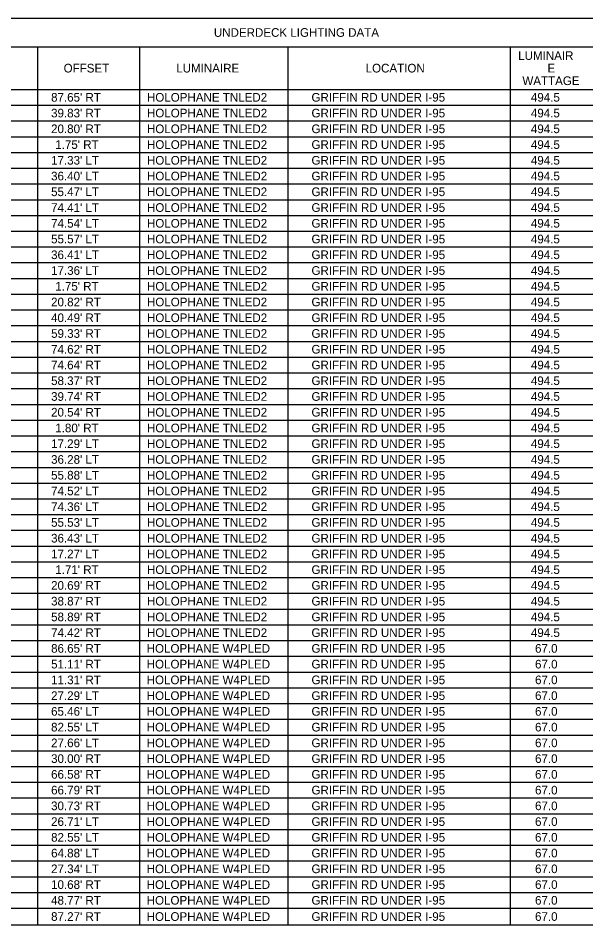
# Model space of a CAD drawing. Extents: x -816.7 to -800.9, y -2209.6 to -2187.8.
# Drawn here: x -810.37 to -805.77, y -2207.45 to -2200.11 of the extents above; entities that cross this region are included whole.
import ezdxf

# ---------------------------------------------------------------- set-up
doc = ezdxf.new("R2010")
doc.units = 0
for name, color, linetype in [('PlotBorder_dp', 7, 'Continuous'), ('SheetBorder_dp', 7, 'Continuous'), ('SheetLines_dp', 7, 'Continuous'), ('TextMinor', 7, 'Continuous')]:
    doc.layers.add(name, color=color, linetype=linetype)

msp = doc.modelspace()

# ---------------------------------------------------------------- linework, layer by layer
at = {"layer": 'PlotBorder_dp'}
for p, q in [((-810.2111, -2200.3435), (-810.2111, -2201.326)), ((-810.2111, -2200.3435), (-810.2111, -2207.4535)), ((-809.3861, -2200.3435), (-809.3861, -2207.4535)), ((-809.3861, -2200.3435), (-809.3861, -2207.4535)), ((-808.1861, -2200.3435), (-808.1861, -2207.4535)), ((-808.1861, -2200.3435), (-808.1861, -2207.4535)), ((-806.3861, -2200.3435), (-806.3861, -2207.4535)), ((-806.3861, -2200.3435), (-806.3861, -2207.4535)), ((-813.1586, -2200.6885), (-802.8536, -2200.6885)), ((-810.2111, -2201.4535), (-810.2111, -2205.7885)), ((-810.2111, -2205.916), (-810.2111, -2207.4535))]:
    msp.add_line(p, q, dxfattribs=at)
at = {"layer": 'SheetLines_dp'}
for p, q in [((-813.1586, -2200.111), (-802.8536, -2200.111)), ((-813.1586, -2200.3435), (-802.8536, -2200.3435)), ((-813.1586, -2200.3435), (-802.8536, -2200.3435)), ((-813.1586, -2207.4535), (-802.8536, -2207.4535))]:
    msp.add_line(p, q, dxfattribs=at)
at = {"layer": 'TextMinor'}
for p, q in [((-813.1586, -2200.6885), (-802.8536, -2200.6885)), ((-813.1586, -2200.816), (-802.8536, -2200.816)), ((-813.1586, -2200.816), (-802.8536, -2200.816)), ((-813.1586, -2200.9435), (-802.8536, -2200.9435)), ((-813.1586, -2200.9435), (-802.8536, -2200.9435)), ((-813.1586, -2201.071), (-802.8536, -2201.071)), ((-813.1586, -2201.071), (-802.8536, -2201.071)), ((-813.1586, -2201.1985), (-802.8536, -2201.1985)), ((-813.1586, -2201.1985), (-802.8536, -2201.1985)), ((-813.1586, -2201.326), (-802.8536, -2201.326)), ((-813.1586, -2201.326), (-802.8536, -2201.326)), ((-813.1586, -2201.4535), (-802.8536, -2201.4535)), ((-810.2111, -2201.4535), (-802.8536, -2201.4535)), ((-813.1586, -2201.581), (-802.8536, -2201.581)), ((-813.1586, -2201.581), (-802.8536, -2201.581)), ((-813.1586, -2201.7085), (-802.8536, -2201.7085)), ((-813.1586, -2201.7085), (-802.8536, -2201.7085)), ((-813.1586, -2201.836), (-802.8536, -2201.836)), ((-813.1586, -2201.836), (-802.8536, -2201.836)), ((-813.1586, -2201.9635), (-802.8536, -2201.9635)), ((-813.1586, -2201.9635), (-802.8536, -2201.9635)), ((-813.1586, -2202.091), (-802.8536, -2202.091)), ((-813.1586, -2202.091), (-802.8536, -2202.091)), ((-813.1586, -2202.2185), (-802.8536, -2202.2185)), ((-813.1586, -2202.2185), (-802.8536, -2202.2185)), ((-813.1586, -2202.346), (-802.8536, -2202.346)), ((-813.1586, -2202.346), (-802.8536, -2202.346)), ((-813.1586, -2202.4735), (-802.8536, -2202.4735)), ((-813.1586, -2202.4735), (-802.8536, -2202.4735)), ((-813.1586, -2202.601), (-802.8536, -2202.601)), ((-813.1586, -2202.601), (-802.8536, -2202.601)), ((-813.1586, -2202.7285), (-802.8536, -2202.7285)), ((-813.1586, -2202.7285), (-802.8536, -2202.7285)), ((-813.1586, -2202.856), (-802.8536, -2202.856)), ((-813.1586, -2202.856), (-802.8536, -2202.856)), ((-813.1586, -2202.9835), (-802.8536, -2202.9835)), ((-813.1586, -2202.9835), (-802.8536, -2202.9835)), ((-813.1586, -2203.111), (-802.8536, -2203.111)), ((-813.1586, -2203.111), (-802.8536, -2203.111)), ((-813.1586, -2203.2385), (-802.8536, -2203.2385)), ((-813.1586, -2203.2385), (-802.8536, -2203.2385)), ((-813.1586, -2203.366), (-802.8536, -2203.366)), ((-813.1586, -2203.366), (-802.8536, -2203.366)), ((-813.1586, -2203.4935), (-802.8536, -2203.4935)), ((-813.1586, -2203.4935), (-802.8536, -2203.4935)), ((-813.1586, -2203.621), (-802.8536, -2203.621)), ((-813.1586, -2203.621), (-802.8536, -2203.621)), ((-813.1586, -2203.7485), (-802.8536, -2203.7485)), ((-813.1586, -2203.7485), (-802.8536, -2203.7485)), ((-813.1586, -2203.876), (-802.8536, -2203.876)), ((-813.1586, -2203.876), (-802.8536, -2203.876)), ((-813.1586, -2204.0035), (-802.8536, -2204.0035)), ((-813.1586, -2204.0035), (-802.8536, -2204.0035)), ((-813.1586, -2204.131), (-802.8536, -2204.131)), ((-813.1586, -2204.131), (-802.8536, -2204.131)), ((-813.1586, -2204.2585), (-802.8536, -2204.2585)), ((-813.1586, -2204.2585), (-802.8536, -2204.2585)), ((-813.1586, -2204.386), (-802.8536, -2204.386)), ((-813.1586, -2204.386), (-802.8536, -2204.386)), ((-813.1586, -2204.5135), (-802.8536, -2204.5135)), ((-813.1586, -2204.5135), (-802.8536, -2204.5135)), ((-813.1586, -2204.641), (-802.8536, -2204.641)), ((-813.1586, -2204.641), (-802.8536, -2204.641)), ((-813.1586, -2204.7685), (-802.8536, -2204.7685)), ((-813.1586, -2204.7685), (-802.8536, -2204.7685)), ((-813.1586, -2204.896), (-802.8536, -2204.896)), ((-813.1586, -2204.896), (-802.8536, -2204.896)), ((-813.1586, -2205.0235), (-802.8536, -2205.0235)), ((-813.1586, -2205.0235), (-802.8536, -2205.0235)), ((-813.1586, -2205.151), (-802.8536, -2205.151)), ((-813.1586, -2205.2785), (-802.8536, -2205.2785)), ((-813.1586, -2205.2785), (-802.8536, -2205.2785)), ((-813.1586, -2205.406), (-802.8536, -2205.406)), ((-813.1586, -2205.406), (-802.8536, -2205.406)), ((-813.1586, -2205.5335), (-802.8536, -2205.5335)), ((-813.1586, -2205.5335), (-802.8536, -2205.5335)), ((-813.1586, -2205.661), (-802.8536, -2205.661)), ((-813.1586, -2205.661), (-802.8536, -2205.661)), ((-813.1586, -2205.7885), (-802.8536, -2205.7885)), ((-813.1586, -2205.7885), (-802.8536, -2205.7885)), ((-813.1586, -2205.916), (-802.8536, -2205.916)), ((-810.2111, -2205.916), (-802.8536, -2205.916)), ((-813.1586, -2206.0435), (-802.8536, -2206.0435)), ((-813.1586, -2206.0435), (-802.8536, -2206.0435)), ((-813.1586, -2206.171), (-802.8536, -2206.171)), ((-813.1586, -2206.171), (-802.8536, -2206.171)), ((-813.1586, -2206.2985), (-802.8536, -2206.2985)), ((-813.1586, -2206.2985), (-802.8536, -2206.2985)), ((-813.1586, -2206.426), (-802.8536, -2206.426)), ((-813.1586, -2206.426), (-802.8536, -2206.426)), ((-813.1586, -2206.5535), (-802.8536, -2206.5535)), ((-813.1586, -2206.5535), (-802.8536, -2206.5535)), ((-813.1586, -2206.681), (-802.8536, -2206.681)), ((-813.1586, -2206.681), (-802.8536, -2206.681)), ((-813.1586, -2206.8085), (-802.8536, -2206.8085)), ((-813.1586, -2206.8085), (-802.8536, -2206.8085)), ((-813.1586, -2206.936), (-802.8536, -2206.936)), ((-813.1586, -2206.936), (-802.8536, -2206.936)), ((-813.1586, -2207.0635), (-802.8536, -2207.0635)), ((-813.1586, -2207.0635), (-802.8536, -2207.0635)), ((-813.1586, -2207.191), (-802.8536, -2207.191)), ((-813.1586, -2207.191), (-802.8536, -2207.191)), ((-813.1586, -2207.3185), (-802.8536, -2207.3185)), ((-813.1586, -2207.3185), (-802.8536, -2207.3185))]:
    msp.add_line(p, q, dxfattribs=at)

# ---------------------------------------------------------------- texts
at = {"layer": 'SheetBorder_dp'}
for s, p in [('UNDERDECK LIGHTING DATA', (-808.7843, -2200.2622)), ('LUMINAIR', (-806.3212, -2200.449)), ('OFFSET', (-810.0001, -2200.551)), ('LUMINAIRE', (-809.0888, -2200.551)), ('LOCATION', (-807.5558, -2200.551)), ('E', (-806.084, -2200.551)), ('WATTAGE', (-806.2873, -2200.653)), ("87.65' RT", (-810.1017, -2200.7872)), ('HOLOPHANE TNLED2', (-809.3257, -2200.7872)), ('GRIFFIN RD UNDER I-95', (-807.9942, -2200.7872)), ('494.5', (-806.2184, -2200.7872)), ("39.83' RT", (-810.1017, -2200.9147)), ('HOLOPHANE TNLED2', (-809.3257, -2200.9147)), ('GRIFFIN RD UNDER I-95', (-807.9942, -2200.9147)), ('494.5', (-806.2184, -2200.9147)), ("20.80' RT", (-810.1017, -2201.0422)), ('HOLOPHANE TNLED2', (-809.3257, -2201.0422)), ('GRIFFIN RD UNDER I-95', (-807.9942, -2201.0422)), ('494.5', (-806.2184, -2201.0422)), ("1.75' RT", (-810.0678, -2201.1697)), ('HOLOPHANE TNLED2', (-809.3257, -2201.1697)), ('GRIFFIN RD UNDER I-95', (-807.9942, -2201.1697)), ('494.5', (-806.2184, -2201.1697)), ("17.33' LT", (-810.1017, -2201.2972)), ('HOLOPHANE TNLED2', (-809.3257, -2201.2972)), ('GRIFFIN RD UNDER I-95', (-807.9942, -2201.2972)), ('494.5', (-806.2184, -2201.2972)), ("36.40' LT", (-810.1017, -2201.4247)), ('HOLOPHANE TNLED2', (-809.3257, -2201.4247)), ('GRIFFIN RD UNDER I-95', (-807.9942, -2201.4247)), ('494.5', (-806.2184, -2201.4247)), ("55.47' LT", (-810.1017, -2201.5522)), ('HOLOPHANE TNLED2', (-809.3257, -2201.5522)), ('GRIFFIN RD UNDER I-95', (-807.9942, -2201.5522)), ('494.5', (-806.2184, -2201.5522)), ("74.41' LT", (-810.1017, -2201.6797)), ('HOLOPHANE TNLED2', (-809.3257, -2201.6797)), ('GRIFFIN RD UNDER I-95', (-807.9942, -2201.6797)), ('494.5', (-806.2184, -2201.6797)), ("74.54' LT", (-810.1017, -2201.8072)), ('HOLOPHANE TNLED2', (-809.3257, -2201.8072)), ('GRIFFIN RD UNDER I-95', (-807.9942, -2201.8072)), ('494.5', (-806.2184, -2201.8072)), ("55.57' LT", (-810.1017, -2201.9347)), ('HOLOPHANE TNLED2', (-809.3257, -2201.9347)), ('GRIFFIN RD UNDER I-95', (-807.9942, -2201.9347)), ('494.5', (-806.2184, -2201.9347)), ("36.41' LT", (-810.1017, -2202.0622)), ('HOLOPHANE TNLED2', (-809.3257, -2202.0622)), ('GRIFFIN RD UNDER I-95', (-807.9942, -2202.0622)), ('494.5', (-806.2184, -2202.0622)), ("17.36' LT", (-810.1017, -2202.1897)), ('HOLOPHANE TNLED2', (-809.3257, -2202.1897)), ('GRIFFIN RD UNDER I-95', (-807.9942, -2202.1897)), ('494.5', (-806.2184, -2202.1897)), ("1.75' RT", (-810.0678, -2202.3172)), ('HOLOPHANE TNLED2', (-809.3257, -2202.3172)), ('GRIFFIN RD UNDER I-95', (-807.9942, -2202.3172)), ('494.5', (-806.2184, -2202.3172)), ("20.82' RT", (-810.1017, -2202.4447)), ('HOLOPHANE TNLED2', (-809.3257, -2202.4447)), ('GRIFFIN RD UNDER I-95', (-807.9942, -2202.4447)), ('494.5', (-806.2184, -2202.4447)), ("40.49' RT", (-810.1017, -2202.5722)), ('HOLOPHANE TNLED2', (-809.3257, -2202.5722)), ('GRIFFIN RD UNDER I-95', (-807.9942, -2202.5722)), ('494.5', (-806.2184, -2202.5722)), ("59.33' RT", (-810.1017, -2202.6997)), ('HOLOPHANE TNLED2', (-809.3257, -2202.6997)), ('GRIFFIN RD UNDER I-95', (-807.9942, -2202.6997)), ('494.5', (-806.2184, -2202.6997)), ("74.62' RT", (-810.1017, -2202.8272)), ('HOLOPHANE TNLED2', (-809.3257, -2202.8272)), ('GRIFFIN RD UNDER I-95', (-807.9942, -2202.8272)), ('494.5', (-806.2184, -2202.8272)), ("74.64' RT", (-810.1017, -2202.9547)), ('HOLOPHANE TNLED2', (-809.3257, -2202.9547)), ('GRIFFIN RD UNDER I-95', (-807.9942, -2202.9547)), ('494.5', (-806.2184, -2202.9547)), ("58.37' RT", (-810.1017, -2203.0822)), ('HOLOPHANE TNLED2', (-809.3257, -2203.0822)), ('GRIFFIN RD UNDER I-95', (-807.9942, -2203.0822)), ('494.5', (-806.2184, -2203.0822)), ("39.74' RT", (-810.1017, -2203.2097)), ('HOLOPHANE TNLED2', (-809.3257, -2203.2097)), ('GRIFFIN RD UNDER I-95', (-807.9942, -2203.2097)), ('494.5', (-806.2184, -2203.2097)), ("20.54' RT", (-810.1017, -2203.3372)), ('HOLOPHANE TNLED2', (-809.3257, -2203.3372)), ('GRIFFIN RD UNDER I-95', (-807.9942, -2203.3372)), ('494.5', (-806.2184, -2203.3372)), ("1.80' RT", (-810.0678, -2203.4647)), ('HOLOPHANE TNLED2', (-809.3257, -2203.4647)), ('GRIFFIN RD UNDER I-95', (-807.9942, -2203.4647)), ('494.5', (-806.2184, -2203.4647)), ("17.29' LT", (-810.1017, -2203.5922)), ('HOLOPHANE TNLED2', (-809.3257, -2203.5922)), ('GRIFFIN RD UNDER I-95', (-807.9942, -2203.5922)), ('494.5', (-806.2184, -2203.5922)), ("36.28' LT", (-810.1017, -2203.7197)), ('HOLOPHANE TNLED2', (-809.3257, -2203.7197)), ('GRIFFIN RD UNDER I-95', (-807.9942, -2203.7197)), ('494.5', (-806.2184, -2203.7197)), ("55.88' LT", (-810.1017, -2203.8472)), ('HOLOPHANE TNLED2', (-809.3257, -2203.8472)), ('GRIFFIN RD UNDER I-95', (-807.9942, -2203.8472)), ('494.5', (-806.2184, -2203.8472)), ("74.52' LT", (-810.1017, -2203.9747)), ('HOLOPHANE TNLED2', (-809.3257, -2203.9747)), ('GRIFFIN RD UNDER I-95', (-807.9942, -2203.9747)), ('494.5', (-806.2184, -2203.9747)), ("74.36' LT", (-810.1017, -2204.1022)), ('HOLOPHANE TNLED2', (-809.3257, -2204.1022)), ('GRIFFIN RD UNDER I-95', (-807.9942, -2204.1022)), ('494.5', (-806.2184, -2204.1022)), ("55.53' LT", (-810.1017, -2204.2297)), ('HOLOPHANE TNLED2', (-809.3257, -2204.2297)), ('GRIFFIN RD UNDER I-95', (-807.9942, -2204.2297)), ('494.5', (-806.2184, -2204.2297)), ("36.43' LT", (-810.1017, -2204.3572)), ('HOLOPHANE TNLED2', (-809.3257, -2204.3572)), ('GRIFFIN RD UNDER I-95', (-807.9942, -2204.3572)), ('494.5', (-806.2184, -2204.3572)), ("17.27' LT", (-810.1017, -2204.4847)), ('HOLOPHANE TNLED2', (-809.3257, -2204.4847)), ('GRIFFIN RD UNDER I-95', (-807.9942, -2204.4847)), ('494.5', (-806.2184, -2204.4847)), ("1.71' RT", (-810.0678, -2204.6122)), ('HOLOPHANE TNLED2', (-809.3257, -2204.6122)), ('GRIFFIN RD UNDER I-95', (-807.9942, -2204.6122)), ('494.5', (-806.2184, -2204.6122)), ("20.69' RT", (-810.1017, -2204.7397)), ('HOLOPHANE TNLED2', (-809.3257, -2204.7397)), ('GRIFFIN RD UNDER I-95', (-807.9942, -2204.7397)), ('494.5', (-806.2184, -2204.7397)), ("38.87' RT", (-810.1017, -2204.8672)), ('HOLOPHANE TNLED2', (-809.3257, -2204.8672)), ('GRIFFIN RD UNDER I-95', (-807.9942, -2204.8672)), ('494.5', (-806.2184, -2204.8672)), ("58.89' RT", (-810.1017, -2204.9947)), ('HOLOPHANE TNLED2', (-809.3257, -2204.9947)), ('GRIFFIN RD UNDER I-95', (-807.9942, -2204.9947)), ('494.5', (-806.2184, -2204.9947)), ("74.42' RT", (-810.1017, -2205.1222)), ('HOLOPHANE TNLED2', (-809.3257, -2205.1222)), ('GRIFFIN RD UNDER I-95', (-807.9942, -2205.1222)), ('494.5', (-806.2184, -2205.1222)), ("86.65' RT", (-810.1017, -2205.2497)), ('HOLOPHANE W4PLED', (-809.3279, -2205.2497)), ('GRIFFIN RD UNDER I-95', (-807.9942, -2205.2497)), ('67.0', (-806.1848, -2205.2497)), ("51.11' RT", (-810.1017, -2205.3772)), ('HOLOPHANE W4PLED', (-809.3279, -2205.3772)), ('GRIFFIN RD UNDER I-95', (-807.9942, -2205.3772)), ('67.0', (-806.1848, -2205.3772)), ("11.31' RT", (-810.1017, -2205.5047)), ('HOLOPHANE W4PLED', (-809.3279, -2205.5047)), ('GRIFFIN RD UNDER I-95', (-807.9942, -2205.5047)), ('67.0', (-806.1848, -2205.5047)), ("27.29' LT", (-810.1017, -2205.6322)), ('HOLOPHANE W4PLED', (-809.3279, -2205.6322)), ('GRIFFIN RD UNDER I-95', (-807.9942, -2205.6322)), ('67.0', (-806.1848, -2205.6322)), ("65.46' LT", (-810.1017, -2205.7597)), ('HOLOPHANE W4PLED', (-809.3279, -2205.7597)), ('GRIFFIN RD UNDER I-95', (-807.9942, -2205.7597)), ('67.0', (-806.1848, -2205.7597)), ("82.55' LT", (-810.1017, -2205.8872)), ('HOLOPHANE W4PLED', (-809.3279, -2205.8872)), ('GRIFFIN RD UNDER I-95', (-807.9942, -2205.8872)), ('67.0', (-806.1848, -2205.8872)), ("27.66' LT", (-810.1017, -2206.0147)), ('HOLOPHANE W4PLED', (-809.3279, -2206.0147)), ('GRIFFIN RD UNDER I-95', (-807.9942, -2206.0147)), ('67.0', (-806.1848, -2206.0147)), ("30.00' RT", (-810.1017, -2206.1422)), ('HOLOPHANE W4PLED', (-809.3279, -2206.1422)), ('GRIFFIN RD UNDER I-95', (-807.9942, -2206.1422)), ('67.0', (-806.1848, -2206.1422)), ("66.58' RT", (-810.1017, -2206.2697)), ('HOLOPHANE W4PLED', (-809.3279, -2206.2697)), ('GRIFFIN RD UNDER I-95', (-807.9942, -2206.2697)), ('67.0', (-806.1848, -2206.2697)), ("66.79' RT", (-810.1017, -2206.3972)), ('HOLOPHANE W4PLED', (-809.3279, -2206.3972)), ('GRIFFIN RD UNDER I-95', (-807.9942, -2206.3972)), ('67.0', (-806.1848, -2206.3972)), ("30.73' RT", (-810.1017, -2206.5247)), ('HOLOPHANE W4PLED', (-809.3279, -2206.5247)), ('GRIFFIN RD UNDER I-95', (-807.9942, -2206.5247)), ('67.0', (-806.1848, -2206.5247)), ("26.71' LT", (-810.1017, -2206.6522)), ('HOLOPHANE W4PLED', (-809.3279, -2206.6522)), ('GRIFFIN RD UNDER I-95', (-807.9942, -2206.6522)), ('67.0', (-806.1848, -2206.6522)), ("82.55' LT", (-810.1017, -2206.7797)), ('HOLOPHANE W4PLED', (-809.3279, -2206.7797)), ('GRIFFIN RD UNDER I-95', (-807.9942, -2206.7797)), ('67.0', (-806.1848, -2206.7797)), ("64.88' LT", (-810.1017, -2206.9072)), ('HOLOPHANE W4PLED', (-809.3279, -2206.9072)), ('GRIFFIN RD UNDER I-95', (-807.9942, -2206.9072)), ('67.0', (-806.1848, -2206.9072)), ("27.34' LT", (-810.1017, -2207.0347)), ('HOLOPHANE W4PLED', (-809.3279, -2207.0347)), ('GRIFFIN RD UNDER I-95', (-807.9942, -2207.0347)), ('67.0', (-806.1848, -2207.0347)), ("10.68' RT", (-810.1017, -2207.1622)), ('HOLOPHANE W4PLED', (-809.3279, -2207.1622)), ('GRIFFIN RD UNDER I-95', (-807.9942, -2207.1622)), ('67.0', (-806.1848, -2207.1622)), ("48.77' RT", (-810.1017, -2207.2897)), ('HOLOPHANE W4PLED', (-809.3279, -2207.2897)), ('GRIFFIN RD UNDER I-95', (-807.9942, -2207.2897)), ('67.0', (-806.1848, -2207.2897)), ("87.27' RT", (-810.1017, -2207.421)), ('HOLOPHANE W4PLED', (-809.3279, -2207.421)), ('GRIFFIN RD UNDER I-95', (-807.9942, -2207.421)), ('67.0', (-806.1848, -2207.421))]:
    msp.add_text(s, height=0.07, dxfattribs=at).set_placement(p)

doc.saveas('drawing.dxf')
